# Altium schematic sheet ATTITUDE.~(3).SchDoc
size A4
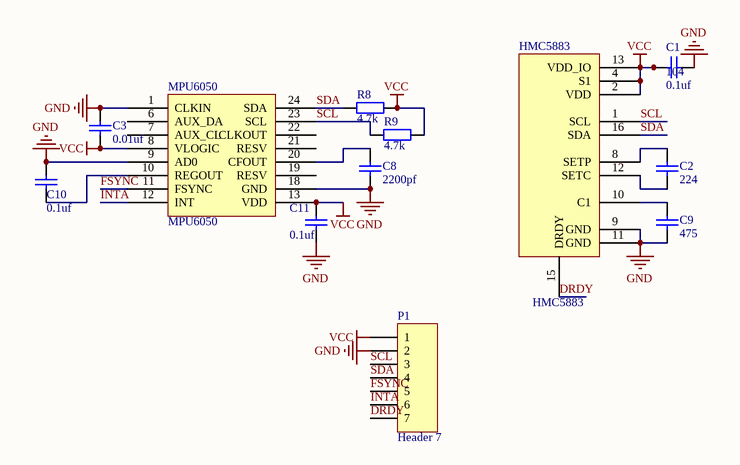
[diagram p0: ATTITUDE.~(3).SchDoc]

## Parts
C1  104  value 0.1uf  [C0805]
C2  224  [C0805]
C3  value 0.01uf  [C0805]  (hidden comment: 0.01)
C8  value 2200pf  [C0805]  (hidden comment: 2.2nF)
C9  475  [C0805]
C10  value 0.1uf  [C0805]  (hidden comment: 104)
C11  value 0.1uf  [C0805]  (hidden comment: 104)
HMC5883  HMC5883  [HMC5883]
MPU6050  MPU6050  [MPU6050]
P1  Header 7  [HDR1X7]
R8  4.7k  [6-0805_M]
R9  4.7k  [6-0805_M]

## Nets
GND: C1.1 C3.1 C8.1 C9.2 C10.1 C11.2 HMC5883.9(GND) HMC5883.11(GND) MPU6050.1(CLKIN) MPU6050.9(AD0) MPU6050.18(GND) P1.2
VCC: C1.2 C3.2 C11.1 HMC5883.2(VDD) HMC5883.4(S1) HMC5883.13(VDD_IO) MPU6050.8(VLOGIC) MPU6050.13(VDD) P1.1 R8.1 R9.2
DRDY: HMC5883.15(DRDY) P1.7
FSYNC: MPU6050.11(FSYNC) P1.5
INTA: MPU6050.12(INT) P1.6
SCL: HMC5883.1(SCL) MPU6050.23(SCL) P1.3 R9.1
SDA: HMC5883.16(SDA) MPU6050.24(SDA) P1.4 R8.2
NetC2_1: C2.1 HMC5883.8(SETP)
NetC2_2: C2.2 HMC5883.12(SETC)
NetC8_2: C8.2 MPU6050.20(CFOUT)
NetC9_1: C9.1 HMC5883.10(C1)
NetC10_2: C10.2 MPU6050.10(REGOUT)

Not connected (* = marked no-connect by the designer): MPU6050 6(AUX_DA) 7(AUX_CL) 19(RESV) 21(RESV) 22(CLKOUT)

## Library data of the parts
C1-C3 C8-C11 = Cap Semi: Capacitor (Semiconductor SIM Model)
HMC5883 MPU6050 = Component_1
P1 = Header 7: Header, 7-Pin
R8 R9 = Res2: Resistor; Value: 0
